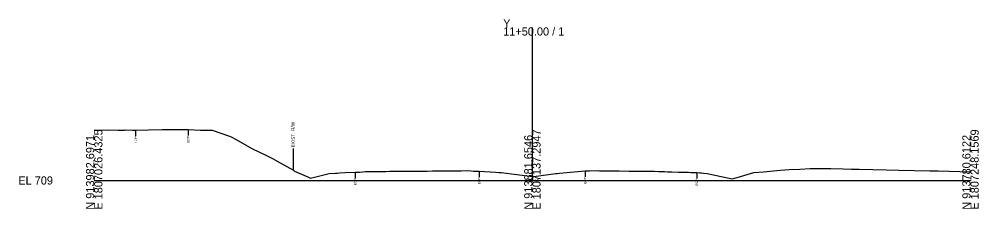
# Model space of a CAD drawing. Extents: x -26 to 3303, y -30 to 9580.
# Drawn here: x -25.7 to 302.8, y 1490.3 to 1555.2 of the extents above; entities that cross this region are included whole.
import ezdxf

# ---------------------------------------------------------------- set-up
doc = ezdxf.new("R2010")
doc.units = 0
for name, color, linetype in [('Exist Cross Section Cell', 7, 'Continuous'), ('Exist XS Center Line Elevation Label', 7, 'Continuous'), ('Exist XS Ground Line', 7, 'Continuous'), ('Old_Level_10', 7, 'Continuous')]:
    doc.layers.add(name, color=color, linetype=linetype)

msp = doc.modelspace()

# ---------------------------------------------------------------- linework, layer by layer
at = {"layer": 'Exist Cross Section Cell'}
for p, q in [((150, 1500), (150, 1552.39)), ((0, 1500), (150, 1500)), ((150, 1500), (300, 1500))]:
    msp.add_line(p, q, dxfattribs=at)
at = {"layer": 'Exist XS Ground Line'}
msp.add_lwpolyline([(0, 1517.24), (1.77, 1517.27), (4.44, 1517.31), (8.19, 1517.26), (9.45, 1517.26), (10.31, 1517.26), (10.73, 1517.28), (13.14, 1517.25), (14.18, 1517.24), (18.57, 1517.34), (23.31, 1517.46), (27.79, 1517.44), (32.13, 1517.41), (36.35, 1517.24), (40.32, 1517.18), (46.29, 1515.13), (46.91, 1514.88), (48.54, 1514), (53.99, 1510.95), (58.95, 1508.57), (61.06, 1507.53), (63.68, 1506.02), (68.18, 1503.51), (68.58, 1503.22), (73.37, 1501.1), (74.03, 1500.81), (79.56, 1502.18), (80.39, 1502.39), (82.57, 1502.5), (83.12, 1502.53), (84.03, 1502.58), (85.88, 1502.68), (89.31, 1502.85), (90.49, 1502.88), (90.97, 1502.89), (91.79, 1502.97), (92.91, 1503.05), (94.1, 1503.06), (95.15, 1503.07), (97.48, 1503.1), (98.56, 1503.11), (99.81, 1503.12), (101.21, 1503.13), (101.58, 1503.13), (101.92, 1503.14), (102.29, 1503.14), (104.36, 1503.15), (105.01, 1503.16), (105.31, 1503.16), (108.71, 1503.2), (110.42, 1503.22), (112.34, 1503.23), (113.97, 1503.24), (115.85, 1503.26), (116.56, 1503.27), (118.85, 1503.3), (119.75, 1503.31), (122.2, 1503.33), (123.5, 1503.34), (124.59, 1503.35), (125.62, 1503.35), (127.58, 1503.38), (129, 1503.28), (129.88, 1503.23), (131.15, 1503.2), (131.78, 1503.19), (137.35, 1502.83), (138.53, 1502.75), (138.94, 1502.73), (139.27, 1502.69), (150, 1501.38), (150.55, 1501.31), (158.06, 1502.4), (158.45, 1502.43), (159.23, 1502.5), (168.09, 1503.25), (168.55, 1503.26), (169.58, 1503.26), (172.27, 1503.36), (172.98, 1503.35), (175.41, 1503.33), (176.36, 1503.32), (179.12, 1503.29), (179.75, 1503.29), (183.09, 1503.24), (184.12, 1503.22), (186.55, 1503.18), (190.27, 1503.15), (191.83, 1503.13), (193.23, 1503.1), (193.59, 1503.1), (194.29, 1503.09), (195.29, 1503.07), (196.23, 1503.01), (196.66, 1502.99), (197.69, 1502.95), (200, 1502.89), (200.65, 1502.87), (201.39, 1502.85), (202.49, 1502.82), (203.44, 1502.79), (204.23, 1502.77), (205.1, 1502.75), (206.33, 1502.72), (207.3, 1502.62), (207.92, 1502.56), (208.54, 1502.51), (209.88, 1502.4), (211.42, 1502.03), (218.35, 1500.54), (220.12, 1501.04), (225.83, 1502.69), (229.18, 1502.99), (234.84, 1503.48), (238.03, 1503.73), (241.53, 1503.89), (245.11, 1504.05), (248.37, 1504.05), (252.19, 1504.06), (256.37, 1503.96), (259.27, 1503.91), (261.9, 1503.82), (271.22, 1503.62), (275.43, 1503.55), (286.06, 1503.32), (288.96, 1503.27), (300, 1503.01)], dxfattribs=at)
at = {"layer": 'Old_Level_10'}
for p, q in [((14.18, 1517.24), (14.18, 1515.19)), ((32.13, 1517.41), (32.13, 1515.36)), ((68.07, 1510.98), (68.07, 1503.57)), ((89.31, 1502.85), (89.31, 1500.8)), ((131.78, 1503.19), (131.78, 1501.14)), ((168.09, 1503.25), (168.09, 1501.2)), ((206.33, 1502.72), (206.33, 1500.67))]:
    msp.add_line(p, q, dxfattribs=at)

# ---------------------------------------------------------------- texts
at = {"layer": 'Exist Cross Section Cell'}
for s, p in [('Y', (140, 1552.39)), ('11+50.00 / 1', (140, 1549.59)), ('EL 709', (-26, 1498.6))]:
    msp.add_text(s, height=2.8, dxfattribs=at).set_placement(p)
for s, p in [('N 913982.6971', (0, 1490)), ('E 1807026.4325', (2.8, 1490)), ('N 913881.6546', (150, 1490)), ('E 1807137.2947', (152.8, 1490)), ('N 913780.6122', (300, 1490)), ('E 1807248.1569', (302.8, 1490))]:
    msp.add_text(s, height=2.8, rotation=90, dxfattribs=at).set_placement(p)
at = {"layer": 'Exist XS Center Line Elevation Label'}
msp.add_text('710.38', height=1, dxfattribs=at).set_placement((147.98, 1499.38))
at = {"layer": 'Old_Level_10'}
for s, height, p in [('EXIST. R/W', 1.181, (68.66, 1511.28)), ('EOP', 0.787, (14.58, 1512.79)), ('EOP', 0.787, (32.53, 1512.97)), ('EOP', 0.787, (89.7, 1498.4)), ('EOP', 0.787, (132.18, 1498.74)), ('EOP', 0.787, (168.49, 1498.81)), ('EOP', 0.787, (206.72, 1498.27))]:
    msp.add_text(s, height=height, rotation=90, dxfattribs=at).set_placement(p)

doc.saveas('drawing.dxf')
